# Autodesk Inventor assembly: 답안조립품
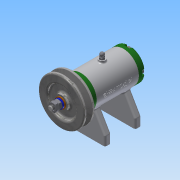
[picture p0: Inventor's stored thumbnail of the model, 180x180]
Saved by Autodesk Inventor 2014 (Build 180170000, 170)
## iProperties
Created: 2018-05
Part Number: 답안조립품
Document SubType Name: Assembly
Designer: net
Author: net
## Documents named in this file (16)
- C:\Users\net\Desktop\480507V1016\답안조립품.iam
- C:\Users\net\Desktop\480507V1016\본체.ipt
- C:\Users\net\Desktop\480507V1016\축.ipt
- C:\Users\net\Desktop\480507V1016\베어링 6002.ipt
- C:\Users\net\Desktop\480507V1016\뒤커버.ipt
- C:\Users\net\Desktop\480507V1016\볼트 M4x12.ipt
- C:\Users\net\Desktop\480507V1016\오일 실 15 25 7.ipt
- C:\Users\net\Desktop\480507V1016\앞커버.ipt
- C:\Users\net\Desktop\480507V1016\키 3x3x12.ipt
- C:\Users\net\Desktop\480507V1016\V벨트풀리.ipt
- C:\Users\net\Desktop\480507V1016\와셔 8x17.ipt
- C:\Users\net\Desktop\480507V1016\스프링와셔 8.ipt
- C:\Users\net\Desktop\480507V1016\너트 M8.ipt
- C:\Users\net\Desktop\480507V1016\니플 M6x0.75.ipt
- C:\Users\net\Desktop\480507V1016\볼트 M6x8.ipt
- C:\Users\net\Desktop\480507V1016\와셔 6x11.5.ipt
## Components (1 placed, 1 different names)
1. V벨트풀리:1
